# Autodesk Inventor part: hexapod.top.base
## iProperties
Created: 2008-10
Part Number: hexapod.top.base
Document SubType Name: Modeling
Designer: Administrator
Density: 1 g/cm^3
Author: Administrator
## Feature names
1. Extrusion1
